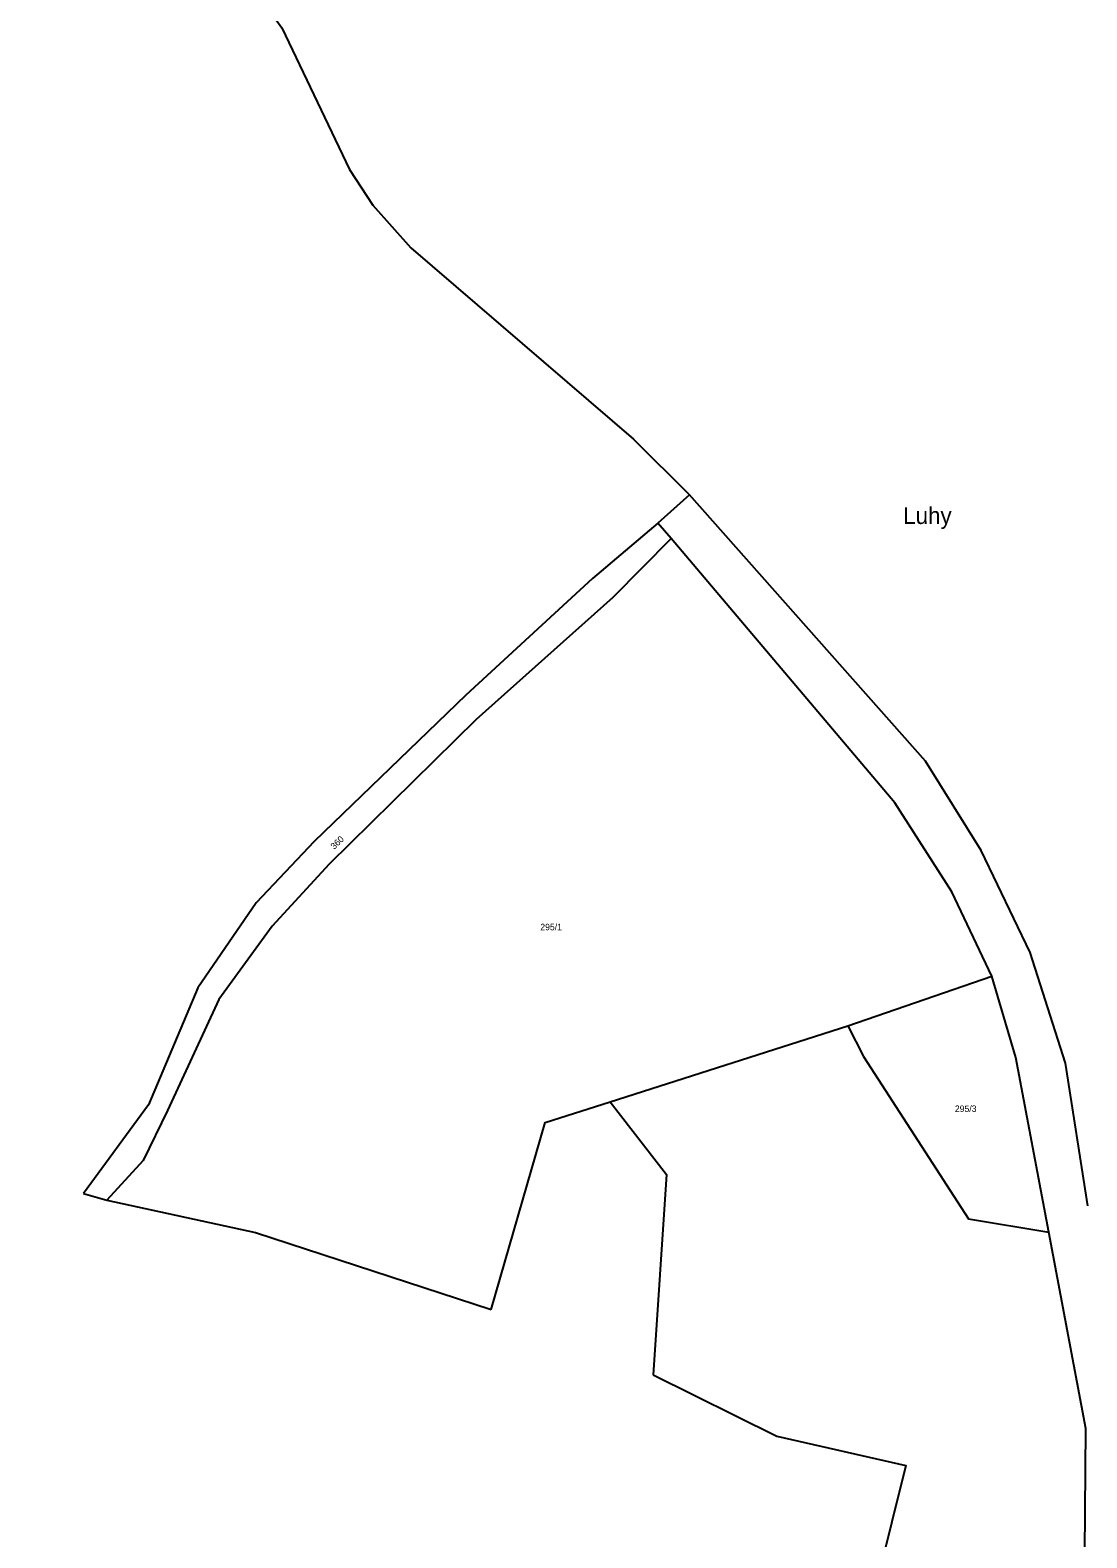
# Model space of a CAD drawing. Extents: x -880531 to -877616, y -1023932 to -1021350.
# Drawn here: x -879082.7 to -878804.4, y -1021964.1 to -1021566.9 of the extents above; entities that cross this region are included whole.
import ezdxf

# ---------------------------------------------------------------- set-up
doc = ezdxf.new("R2010")
doc.units = 0
for name, color, linetype in [('Hranice parcel', 7, 'Continuous'), ('Parcelní čísla', 7, 'Continuous'), ('Pop  PČ popisy', 7, 'Continuous')]:
    doc.layers.add(name, color=color, linetype=linetype)

msp = doc.modelspace()

# ---------------------------------------------------------------- linework, layer by layer
at = {"layer": 'Hranice parcel'}
for p, q in [((-878908.97, -1021689.26), (-878917.34, -1021696.72)), ((-878913.79, -1021700.78), (-878917.34, -1021696.72)), ((-878867.31, -1021829.16), (-878829.38, -1021816.09)), ((-878929.89, -1021849.18), (-878867.31, -1021829.16)), ((-879068.59, -1021873.31), (-879062.47, -1021875.14))]:
    msp.add_line(p, q, dxfattribs=at)
for points in [[(-879082.65, -1021485.89), (-879033.67, -1021541.98), (-879016.4, -1021566.23), (-878998.53, -1021603.55)], [(-878998.53, -1021603.55), (-878992.44, -1021612.99), (-878982.38, -1021624.2)], [(-878982.38, -1021624.2), (-878923.78, -1021674.62), (-878908.97, -1021689.26)], [(-878804.12, -1021876.63), (-878809.97, -1021839.01), (-878819.28, -1021809.84), (-878832.16, -1021783), (-878846.89, -1021759.47), (-878908.97, -1021689.26)], [(-878917.34, -1021696.72), (-878934.55, -1021711.3), (-878967.91, -1021742.04), (-879007.82, -1021780.63), (-879023.11, -1021796.75), (-879038.5, -1021819.14), (-879051.5, -1021850), (-879068.59, -1021873.31)], [(-878913.79, -1021700.78), (-878929.21, -1021716.29), (-878965.22, -1021748.47), (-879003.93, -1021786.58), (-879018.92, -1021802.94), (-879032.96, -1021822.22), (-879046.48, -1021851.44), (-879052.93, -1021864.64), (-879062.47, -1021875.14)], [(-878829.38, -1021816.09), (-878839.9, -1021793.87), (-878854.91, -1021770.41), (-878913.79, -1021700.78)], [(-878814.36, -1021883.57), (-878823.05, -1021837.54), (-878829.38, -1021816.09)], [(-878867.31, -1021829.16), (-878863.2, -1021837.27), (-878835.53, -1021880.03), (-878814.36, -1021883.57)], [(-878961.2, -1021903.94), (-878947.01, -1021854.62), (-878929.89, -1021849.18)], [(-878929.89, -1021849.18), (-878915.08, -1021868.33), (-878918.54, -1021921.07)], [(-879062.47, -1021875.14), (-879023.32, -1021883.61), (-878961.2, -1021903.94)], [(-878813.39, -1022128.85), (-878807.94, -1022061.6), (-878805.1, -1021989.82), (-878804.59, -1021935.28), (-878814.36, -1021883.57)], [(-878918.54, -1021921.07), (-878885.98, -1021937.26), (-878851.99, -1021945.01), (-878863.08, -1021989.53), (-878894.11, -1021990.84), (-878891.57, -1022024.26)]]:
    msp.add_lwpolyline(points, dxfattribs=at)

# ---------------------------------------------------------------- texts
at = {"layer": 'Parcelní čísla'}
msp.add_text('360', height=1.7, rotation=44, dxfattribs=at).set_placement((-879002.559, -1021782.821))
for s, p in [('295/1', (-878948.29, -1021803.99)), ('295/3', (-878839.11, -1021851.86))]:
    msp.add_text(s, height=1.7, dxfattribs=at).set_placement(p)
at = {"layer": 'Pop  PČ popisy'}
msp.add_text('Luhy', height=4.4, dxfattribs=at).set_placement((-878852.72, -1021696.96))

doc.saveas('drawing.dxf')
